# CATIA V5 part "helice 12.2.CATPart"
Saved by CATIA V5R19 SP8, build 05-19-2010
Part number: helice 12.2
Bounding box of the stored display mesh (mm): x -17.321 to 17.321, y -30 to 195, z -10 to 20
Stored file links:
  G:\EU_thinkMotion\CFAO_2010\MMS_groupe2\MMS_groupe2\A reprendre\splanchenault\Planchenault\helice 12.2.CATPart
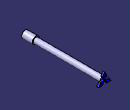
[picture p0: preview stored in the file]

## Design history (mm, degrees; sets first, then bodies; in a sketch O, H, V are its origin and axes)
Body1 (main body)
  Sketch1 on yz-plane, origin (0, 0, 0), H (0, 1, 0), V (0, 0, 1)
    line L1 (0, 0) -> (-30, 0)
    line L2 (-30, 0) -> (-30, -10)
    line L3 (-30, -10) -> (0, -10)
    point P3 (0, -10)
    line L4 (0, -10) -> (0, -7.5)
    line L5 (0, -7.5) -> (190, -7.5)
    line L6 (190, -7.5) -> (190, 0)
    point P6 (190, 0)
    line L7 (190, 0) -> (0, 0)
    length L7 = 190
    length L2 = 10
    length L6 = 7.5
    horizontal: L1 H, L3 H, L5 H, L7 H
    vertical: L2 V, L4 V, L6 V
    coincidence: P3 V, P6 H
  Shaft1: profile Sketch1, axis Sketch1.L1, angle 360
  Sketch2 on face of Shaft1 from Sketch1.L6, origin (0, 190, 0), H (-1, 0, 0), V (0, 0, 1)
    construction line L1 (27.3861, -15.8114) -> (-27.3861, 15.8114)
    axis line L2 (-19.3649, -11.1803) -> (19.3649, 11.1803)
    line L3 (0, 0) -> (5.7735, 10)
    point P5 (5.7735, 10)
    line L4 (5.7735, 10) -> (0, 20)
    point P6 (0, 20)
    line L5 (0, 20) -> (-5.7735, 10)
    point P7 (-5.7735, 10)
    line L6 (-5.7735, 10) -> (0, 0)
    point P8 (5.7735, -10)
    point P9 (17.3205, -10)
    line L7 (17.3205, -10) -> (5.7735, -10)
    point P10 (11.547, 0)
    line L8 (11.547, 0) -> (17.3205, -10)
    point P11 (0, 0)
    line L9 (0, 0) -> (11.547, 0)
    line L10 (5.7735, -10) -> (0, 0)
    point P12 (-11.547, 0)
    point P13 (-17.3205, -10)
    line L11 (-17.3205, -10) -> (-11.547, 0)
    point P14 (0, 0)
    line L12 (-11.547, 0) -> (0, 0)
    point P15 (-5.7735, -10)
    line L13 (0, 0) -> (-5.7735, -10)
    line L14 (-5.7735, -10) -> (-17.3205, -10)
    angle L1 V = 60
    angle L2 V = 60
    perpendicularity: L3 L1, L4 L2
    parallelism: L5 L3, L6 L4
    symmetry: P7 P8 L2, P6 P9 L2, L5 L7 L2, P5 P10 L2, L4 L8 L2, O P11 L2, L3 L9 L2, L6 L10 L2, P7 P12 L1, P6 P13 L1, L5 L11 L1, O P14 L1, L6 L12 L1, P5 P15 L1, L3 L13 L1, L4 L14 L1
    coincidence: O P11, O P14, P11 P14
  Pad1: profile Sketch2, direction (0, 1, 0), length 5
